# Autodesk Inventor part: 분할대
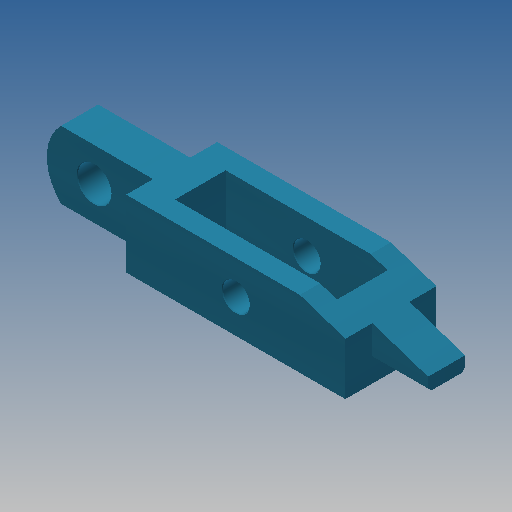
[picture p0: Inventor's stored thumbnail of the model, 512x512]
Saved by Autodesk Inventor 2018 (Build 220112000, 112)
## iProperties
Created: 2016-11
Part Number: 분할대
Material: 강철, 연강
Document SubType Name: Modeling
Designer: mduedu
Density: 1 g/cm^3
Appearance: 터키옥색
Author: mduedu
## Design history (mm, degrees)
sketch "스케치1"
  geometry: L1 (32.5, 13.5)-(-32.5, 13.5); L2 (-32.5, 13.5)-(-32.5, -13.5); L3 (-32.5, -13.5)-(32.5, -13.5); L4 (32.5, -13.5)-(32.5, 13.5); L5 (24, 7.5)-(-24, 7.5); L6 (-24, 7.5)-(-24, -7.5); L7 (-24, -7.5)-(24, -7.5); L8 (24, -7.5)-(24, 7.5); L9 (24, 0)-(-24, 0); L10 (0, -13.5)-(0, 13.5); 4 further points
  constraints: 20 end point, 7 midpoint, 4 parallel, 2 coincident, 2 horizontal, 2 perpendicular, 1 horizontal alignment
  dimensions: "d0" = 15 distance of L5.end L6.end; "d2" = 27 distance between parallel lines of L1 L3; "d3" = 48 distance of L5.start L5.end; "d4" = 65 distance of L1.start L1.end
extrude "돌출1" new body sketch "스케치1" distance "d5" = 20; taper "d6" = 0 deg
sketch "스케치2"
  geometry: L1 (0, 0)-(65, 0) reference; L2 (65, 0)-(65, 20) reference; L3 (0, 20)-(65, 20) reference; L4 (0, 0)-(0, 20) reference; L5 (32.5, 0)-(32.5, 20); C1 r 4 at (32.5, 10)
  constraints: 2 end point, 2 midpoint, 1 centre point
  dimensions: "d7" = 8 diameter of C1
extrude "돌출2" cut sketch "스케치2" extent not by distance; stored distance "d8" = 20; taper "d9" = 0 deg
chamfer "모따기1" distance "d10" = 0.2; stored, may be unused: second distance "d11" = 2, angle "d12" = 45 deg
sketch "스케치3"
  geometry: L1 (-32.5, 0)-(-32.5, 20) reference; L2 (-32.5, 20)-(-59.798, 20); L3 (-64, 20)-(-64, 0); L4 (-64, 0)-(-59.798, 0); L5 (-32.5, 0)-(-32.5, 20); L6 (-59.798, 20)-(-64, 20); L7 (-59.798, 0)-(-32.5, 0); C1 r 4.2 at (0, 10) reference; C2 r 5 at (-50, 10); A1 r 14 centre (-50, 10) between (-59.798, 20) and (-59.798, 0); 1 further point
  constraints: 12 end point, 5 parallel, 2 centre point, 2 horizontal, 2 perpendicular, 2 point on circle, 1 coincident, 1 horizontal alignment, 1 tangent
  dimensions: "d13" = 64 distance from line of L3 C1.centre; "d14" = 14 radius of A1; "d15" = 10 diameter of C2
extrude "돌출3" join sketch "스케치3" stored distance "d16" = 11; taper "d17" = 0 deg
sketch "스케치4"
  geometry: L1 (32.5, 0)-(32.5, 20) reference; L2 (32.5, 20)-(49, 20); L3 (49, 20)-(49, 6); L4 (49, 6)-(32.5, 6); L5 (32.5, 6)-(32.5, 20); L6 (32.5, 0)-(-32.5, 0) reference; 1 further point
  constraints: 8 end point, 2 parallel, 1 horizontal, 1 perpendicular
  dimensions: "d18" = 16.5 distance of L1.end L2.end; "d19" = 6 distance between parallel lines of L4 L6
extrude "돌출4" join sketch "스케치4" stored distance "d20" = 11; taper "d21" = 0 deg
chamfer "모따기2" distance "d22" = 30; stored, may be unused: second distance "d23" = 10, angle "d24" = 45 deg
chamfer "모따기3" distance "d25" = 1; stored, may be unused: second distance "d26" = 10, angle "d27" = 45 deg
chamfer "모따기4" distance "d28" = 0.2; stored, may be unused: second distance "d29" = 10, angle "d30" = 45 deg
node "솔리드1"
node "투영된 루프1"
